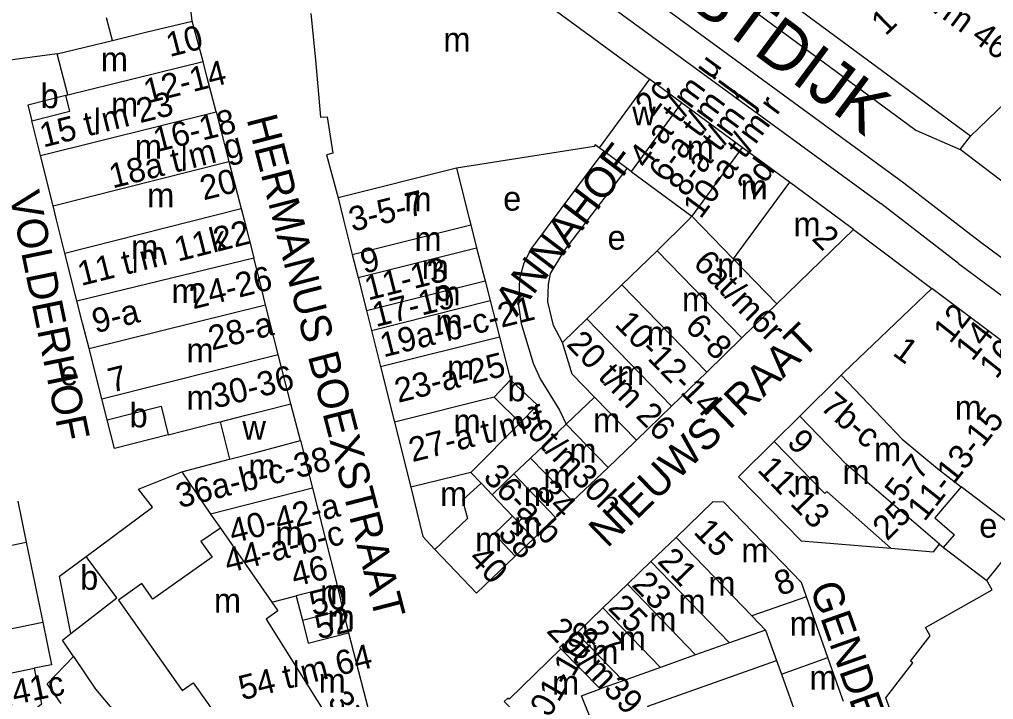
# Model space of a CAD drawing. Extents: x 160673 to 161924, y 382258 to 384145.
# Drawn here: x 161278.7 to 161438.4, y 383421.3 to 383532.8 of the extents above; entities that cross this region are included whole.
import ezdxf

# ---------------------------------------------------------------- set-up
doc = ezdxf.new("R2010")
doc.units = 0
for name, color, linetype in [('BLT_Basislijn', 7, 'Continuous'), ('BLT_Bebouwing', 7, 'Continuous'), ('BLT_Centroide', 7, 'Continuous'), ('BLT_Huisnummer', 7, 'Continuous'), ('BLT_Huisnummer_ tussenligend', 7, 'Continuous'), ('BLT_Huisnummer_reeks', 7, 'Continuous'), ('BLT_Onderdoorgang_en_onderverdeling', 7, 'Continuous'), ('BLT_Onderverdeling_panden', 7, 'Continuous'), ('BLT_Straatnaam', 7, 'Continuous'), ('BLT_Straatnaam_hoofdweg', 7, 'Continuous'), ('BLT_Vlakafsluiter', 7, 'Continuous')]:
    doc.layers.add(name, color=color, linetype=linetype)

msp = doc.modelspace()

# ---------------------------------------------------------------- linework, layer by layer
at = {"layer": 'BLT_Basislijn'}
msp.add_line((161430.2, 383446.26), (161437.31, 383440.84), dxfattribs=at)
for points in [[(161345.39, 383566.33), (161348.12, 383562.88), (161350.96, 383559.81), (161364.55, 383549.36), (161422.89, 383506.67), (161423.67, 383506.07)], [(161347.91, 383555.85), (161361.55, 383545.36), (161419.89, 383502.67)], [(161369.68, 383555.99), (161425.66, 383514.72), (161432.94, 383511.55)], [(161374.48, 383511.24), (161362.64, 383495.36), (161361.37, 383492.9), (161360.66, 383490.37), (161360.51, 383485.96), (161360.94, 383482.97), (161362.91, 383476.51), (161364.04, 383473.9), (161367.23, 383468.78), (161368.3, 383466.51)], [(161367.7, 383479.86), (161366.24, 383482.67), (161365.29, 383486.53), (161365.41, 383489.41), (161365.73, 383491.21), (161368.06, 383494.98), (161378.31, 383508.42)], [(161436.1, 383496.48), (161454.95, 383482.53), (161459.95, 383478.36), (161466.74, 383471.9), (161479.46, 383456.84), (161487.69, 383443.66), (161492.15, 383435.49)], [(161432.63, 383492.84), (161451.85, 383478.6), (161456.62, 383474.62), (161463.1, 383468.46), (161475.41, 383453.89), (161483.38, 383441.14), (161514.75, 383383.64)]]:
    msp.add_lwpolyline(points, dxfattribs=at)
at = {"layer": 'BLT_Bebouwing'}
for p, q in [((161307.01, 383532.58), (161305.61, 383544.29)), ((161354.7, 383543.03), (161376.75, 383526.88)), ((161308.77, 383525.95), (161307.01, 383532.58)), ((161326.43, 383533.81), (161327.24, 383526.25)), ((161284.87, 383527.21), (161270.68, 383525.31)), ((161376.75, 383526.88), (161381.98, 383523.04)), ((161387.23, 383519.16), (161381.98, 383523.04)), ((161286.25, 383520.38), (161286.6, 383520.47)), ((161397.18, 383511.85), (161387.23, 383519.16)), ((161310.92, 383517.7), (161313.02, 383509.56)), ((161282.12, 383510.56), (161280.7, 383516.22)), ((161373.71, 383511.81), (161373.08, 383512.28)), ((161404.93, 383506.15), (161397.18, 383511.85)), ((161284.19, 383502.28), (161282.12, 383510.56)), ((161378.31, 383508.42), (161374.48, 383511.24)), ((161313.02, 383509.56), (161315.02, 383501.84)), ((161378.96, 383507.94), (161378.31, 383508.42)), ((161378.96, 383507.94), (161388.92, 383500.6)), ((161352.66, 383499.2), (161353.63, 383495.43)), ((161402.88, 383486.22), (161415.45, 383498.42)), ((161288.1, 383486.74), (161286.13, 383494.52)), ((161333.25, 383494.32), (161334.2, 383490.55)), ((161353.63, 383495.43), (161355.02, 383490)), ((161377.47, 383489.34), (161383.23, 383494.93)), ((161317.96, 383490.35), (161317.08, 383493.79)), ((161319.04, 383486.08), (161317.96, 383490.35)), ((161334.2, 383490.55), (161335.57, 383485.11)), ((161355.02, 383490), (161355.85, 383486.76)), ((161371.7, 383483.74), (161377.47, 383489.34)), ((161447.99, 383473.94), (161428.25, 383488.75)), ((161289.03, 383483.06), (161288.1, 383486.74)), ((161321.1, 383477.92), (161319.04, 383486.08)), ((161355.85, 383486.76), (161357.37, 383480.83)), ((161397.12, 383480.62), (161402.88, 383486.22)), ((161335.57, 383485.11), (161336.38, 383481.86)), ((161290.08, 383478.91), (161289.03, 383483.06)), ((161367.7, 383479.86), (161371.7, 383483.74)), ((161336.38, 383481.86), (161337.87, 383475.93)), ((161357.37, 383480.83), (161359.18, 383473.77)), ((161391.36, 383475.03), (161397.12, 383480.62)), ((161292.18, 383470.65), (161290.08, 383478.91)), ((161323.15, 383469.83), (161321.1, 383477.92)), ((161337.87, 383475.93), (161340.17, 383466.82)), ((161385.59, 383469.43), (161391.36, 383475.03)), ((161413.4, 383474.51), (161406.61, 383467.78)), ((161293.05, 383467.19), (161292.18, 383470.65)), ((161368.3, 383466.51), (161372.94, 383470.93)), ((161324.75, 383463.8), (161323.15, 383469.83)), ((161379.83, 383463.84), (161385.59, 383469.43)), ((161310.75, 383466.69), (161311.57, 383466.9)), ((161311.57, 383466.9), (161313.13, 383460.74)), ((161406.61, 383467.78), (161402.45, 383463.67)), ((161303.06, 383464.74), (161310.75, 383466.69)), ((161360.76, 383466.71), (161352.71, 383458.55)), ((161362.48, 383460.94), (161368.3, 383466.51)), ((161324.75, 383463.8), (161326.72, 383455.99)), ((161305.27, 383458.7), (161313.13, 383460.74)), ((161359.74, 383458.33), (161362.48, 383460.94)), ((161369.37, 383453.85), (161375.2, 383459.41)), ((161352.71, 383458.55), (161354.39, 383456.79)), ((161356.17, 383454.92), (161359.74, 383458.33)), ((161326.72, 383455.99), (161330.76, 383440.04)), ((161354.39, 383456.79), (161356.17, 383454.92)), ((161433.1, 383456.22), (161428.75, 383451.14)), ((161278.41, 383453.87), (161279.79, 383447.15)), ((161366.57, 383451.17), (161369.37, 383453.85)), ((161363.01, 383447.77), (161366.57, 383451.17)), ((161428.75, 383451.14), (161431.99, 383448.34)), ((161359.97, 383444.87), (161363.01, 383447.77)), ((161386.34, 383447.93), (161382.22, 383443.96)), ((161430.2, 383446.26), (161431.99, 383448.34)), ((161279.79, 383447.15), (161282.48, 383434.02)), ((161382.22, 383443.96), (161378.35, 383440.23)), ((161330.76, 383440.04), (161331.71, 383436.03)), ((161378.35, 383440.23), (161374.35, 383436.37)), ((161438.17, 383439.33), (161437.31, 383440.84)), ((161411.23, 383428.23), (161407.71, 383438.2)), ((161331.71, 383436.03), (161332.65, 383432.28)), ((161374.35, 383436.37), (161370.08, 383432.24)), ((161332.65, 383432.28), (161336.29, 383418.13))]:
    msp.add_line(p, q, dxfattribs=at)
for points in [[(161434.59, 383513.69), (161370.22, 383561.27)], [(161450.34, 383528.87), (161434.59, 383513.69)], [(161286.6, 383520.47), (161284.87, 383527.21)], [(161327.24, 383526.25), (161328.05, 383516.81), (161329.1, 383516.91), (161330.05, 383510.93), (161329.02, 383510.67), (161330.92, 383503.58)], [(161310.92, 383517.7), (161309.42, 383523.48), (161308.77, 383525.95)], [(161286.25, 383520.38), (161280.05, 383518.79), (161280.7, 383516.22)], [(161373.08, 383512.28), (161372.91, 383512.04), (161350.32, 383508.45)], [(161374.48, 383511.24), (161373.96, 383511.63), (161373.71, 383511.81)], [(161350.32, 383508.45), (161352.46, 383500), (161352.66, 383499.2)], [(161415.45, 383498.42), (161413.3, 383500), (161404.93, 383506.15)], [(161286.13, 383494.52), (161284.77, 383500), (161284.19, 383502.28)], [(161330.92, 383503.58), (161331.82, 383500), (161333.25, 383494.32)], [(161315.02, 383501.84), (161315.49, 383500), (161317.08, 383493.79)], [(161383.23, 383494.93), (161388.39, 383500), (161388.92, 383500.6)], [(161428.25, 383488.75), (161413.87, 383474.97), (161413.4, 383474.51)], [(161372.94, 383470.93), (161369.29, 383474.69), (161367.7, 383479.86)], [(161359.18, 383473.77), (161363.6, 383469.58), (161360.76, 383466.71)], [(161303.06, 383464.74), (161294.24, 383462.5), (161293.05, 383467.19)], [(161340.17, 383466.82), (161342.85, 383456.15)], [(161375.2, 383459.41), (161379.49, 383463.51), (161379.83, 383463.84)], [(161402.45, 383463.67), (161396.6, 383457.88), (161406.84, 383447.36), (161421.58, 383446.15)], [(161289.6, 383444.8), (161300.47, 383452.88), (161298.21, 383455.82), (161305.27, 383458.7)], [(161342.85, 383456.15), (161344.83, 383448.05), (161346.77, 383445.92)], [(161443.34, 383448.4), (161433.1, 383456.22)], [(161407.71, 383438.2), (161406.89, 383440.52), (161394.17, 383453.71), (161392.37, 383453.75), (161386.34, 383447.93)], [(161437.31, 383440.84), (161443.34, 383448.4)], [(161421.58, 383446.15), (161428.55, 383445.58), (161429.54, 383446.81)], [(161429.54, 383446.81), (161430.2, 383446.26)], [(161287.12, 383432.15), (161285.26, 383441.57), (161289.6, 383444.8)], [(161346.77, 383445.92), (161353.59, 383438.78), (161359.97, 383444.87)], [(161428.73, 383399.62), (161420.71, 383421.64), (161425.14, 383427.34), (161424.78, 383427.61), (161427.99, 383431.78), (161427.23, 383433.15), (161438.17, 383439.33)], [(161282.48, 383434.02), (161283.91, 383427.04), (161281.07, 383426.46)], [(161287.51, 383428.42), (161285.72, 383431.07), (161287.12, 383432.15)], [(161370.08, 383432.24), (161367.96, 383430.21), (161367.81, 383430.45), (161367.21, 383429.87), (161367.45, 383429.66)], [(161367.45, 383429.66), (161358.98, 383421.38), (161358.74, 383421.59), (161358.13, 383421.03), (161358.29, 383420.86), (161359.67, 383419.42)], [(161285.52, 383420.68), (161283.19, 383423.93), (161287.51, 383428.42)], [(161413.8, 383421), (161411.94, 383426.23), (161411.23, 383428.23)], [(161281.07, 383426.46), (161282.28, 383420.56), (161279.09, 383417.99)]]:
    msp.add_lwpolyline(points, dxfattribs=at)
at = {"layer": 'BLT_Onderdoorgang_en_onderverdeling'}
for p, q in [((161381.98, 383523.04), (161373.71, 383511.81)), ((161387.23, 383519.16), (161378.96, 383507.94))]:
    msp.add_line(p, q, dxfattribs=at)
at = {"layer": 'BLT_Onderverdeling_panden'}
for p, q in [((161299.4, 383530.75), (161307.01, 383532.58)), ((161293.9, 383529.42), (161299.4, 383530.75)), ((161286.6, 383520.47), (161308.77, 383525.95)), ((161282.12, 383510.56), (161310.92, 383517.7)), ((161397.18, 383511.85), (161388.92, 383500.6)), ((161284.19, 383502.28), (161313.02, 383509.56)), ((161350.32, 383508.45), (161330.92, 383503.58)), ((161404.93, 383506.15), (161395.71, 383493.61)), ((161286.13, 383494.52), (161315.02, 383501.84)), ((161388.92, 383500.6), (161395.71, 383493.61)), ((161333.25, 383494.32), (161352.66, 383499.2)), ((161334.2, 383490.55), (161353.63, 383495.43)), ((161383.23, 383494.93), (161397.12, 383480.62)), ((161288.1, 383486.74), (161317.08, 383493.79)), ((161395.71, 383493.61), (161402.88, 383486.22)), ((161335.57, 383485.11), (161355.02, 383490)), ((161377.47, 383489.34), (161391.36, 383475.03)), ((161290.08, 383478.91), (161319.04, 383486.08)), ((161336.38, 383481.86), (161355.85, 383486.76)), ((161371.7, 383483.74), (161385.59, 383469.43)), ((161337.87, 383475.93), (161357.37, 383480.83)), ((161292.18, 383470.65), (161321.1, 383477.92)), ((161372.94, 383470.93), (161379.83, 383463.84)), ((161293.05, 383467.19), (161301.88, 383469.42)), ((161301.88, 383469.42), (161303.06, 383464.74)), ((161315.79, 383467.96), (161318.43, 383468.64)), ((161318.43, 383468.64), (161323.15, 383469.83)), ((161311.57, 383466.9), (161315.79, 383467.96)), ((161368.3, 383466.51), (161375.2, 383459.41)), ((161313.13, 383460.74), (161317.41, 383461.86)), ((161362.48, 383460.94), (161369.37, 383453.85)), ((161429.23, 383459.23), (161433.1, 383456.22)), ((161305.27, 383458.7), (161309.99, 383451.75)), ((161352.71, 383458.55), (161342.85, 383456.15)), ((161359.74, 383458.33), (161366.57, 383451.17)), ((161326.72, 383455.99), (161309.99, 383451.75)), ((161356.17, 383454.92), (161359.54, 383451.4)), ((161309.99, 383451.75), (161311.62, 383449.44)), ((161359.54, 383451.4), (161363.01, 383447.77)), ((161311.62, 383449.44), (161320.03, 383437.33)), ((161386.34, 383447.93), (161398.78, 383435.06)), ((161259.88, 383443.08), (161279.79, 383447.15)), ((161294.65, 383438), (161289.6, 383444.8)), ((161382.22, 383443.96), (161395.11, 383430.63)), ((161330.76, 383440.04), (161324.06, 383438.35)), ((161378.35, 383440.23), (161389.54, 383428.65)), ((161320.03, 383437.33), (161324.06, 383438.35)), ((161324.06, 383438.35), (161324.12, 383438.09)), ((161407.71, 383438.2), (161398.78, 383435.06)), ((161287.12, 383432.15), (161294.65, 383438)), ((161324.12, 383438.09), (161325.07, 383434.35)), ((161325.07, 383434.35), (161331.71, 383436.03)), ((161374.35, 383436.37), (161383.79, 383426.61)), ((161398.78, 383435.06), (161401.02, 383432.74)), ((161262.56, 383429.95), (161282.48, 383434.02)), ((161370.08, 383432.24), (161377.65, 383424.42)), ((161401.02, 383432.74), (161395.11, 383430.63)), ((161401.02, 383432.74), (161402.8, 383427.74)), ((161395.11, 383430.63), (161389.54, 383428.65)), ((161367.45, 383429.66), (161373.88, 383423.08)), ((161389.54, 383428.65), (161383.79, 383426.61)), ((161402.8, 383427.74), (161403.6, 383425.51)), ((161403.6, 383425.51), (161411.23, 383428.23)), ((161263.99, 383422.97), (161281.07, 383426.46)), ((161383.79, 383426.61), (161377.65, 383424.42)), ((161403.6, 383425.51), (161406.17, 383418.29)), ((161377.65, 383424.42), (161373.88, 383423.08))]:
    msp.add_line(p, q, dxfattribs=at)
for points in [[(161293.9, 383529.42), (161292.96, 383533.11)], [(161284.87, 383527.21), (161293.9, 383529.42)], [(161280.7, 383516.22), (161286.91, 383517.81), (161286.25, 383520.38)], [(161359.18, 383473.77), (161356.49, 383470.92), (161340.17, 383466.82)], [(161360.76, 383466.71), (161356.49, 383470.92), (161359.18, 383473.77)], [(161413.4, 383474.51), (161423.42, 383464.05), (161429.23, 383459.23)], [(161429.54, 383446.81), (161414.25, 383459.91), (161406.61, 383467.78)], [(161317.41, 383461.86), (161324.75, 383463.8)], [(161402.45, 383463.67), (161410.74, 383455.12), (161411.08, 383455.44), (161421.58, 383446.15)], [(161354.39, 383456.79), (161351.33, 383454.01), (161352.12, 383451.03), (161346.77, 383445.92)], [(161359.97, 383444.87), (161356.51, 383448.5), (161359.54, 383451.4)], [(161311.62, 383449.44), (161308.43, 383447.26), (161310.25, 383444.66), (161300.53, 383437.82), (161298.75, 383440.35), (161294.9, 383437.64), (161305.36, 383422.81), (161307.15, 383424.08), (161319.74, 383406.42)], [(161320.03, 383437.33), (161321.05, 383435.86), (161319.13, 383434.53), (161331.52, 383414.75)], [(161325.07, 383434.35), (161326.01, 383430.6), (161332.65, 383432.28)], [(161287.51, 383428.42), (161291.14, 383423.03), (161295.87, 383417.4), (161309.52, 383398.77)], [(161375.84, 383403.65), (161383.36, 383416.18), (161381.72, 383420.23), (161402.8, 383427.74)], [(161372.33, 383418.28), (161370.84, 383421.95), (161373.64, 383422.99), (161373.88, 383423.08)]]:
    msp.add_lwpolyline(points, dxfattribs=at)
at = {"layer": 'BLT_Vlakafsluiter'}
for p, q in [((161432.94, 383511.55), (161434.59, 383513.69)), ((161443.28, 383503.61), (161432.94, 383511.55)), ((161423.67, 383506.07), (161436.1, 383496.48)), ((161432.63, 383492.84), (161419.89, 383502.67)), ((161415.45, 383498.42), (161428.25, 383488.75))]:
    msp.add_line(p, q, dxfattribs=at)

# ---------------------------------------------------------------- texts
at = {"layer": 'BLT_Centroide'}
for s, p in [('m', (161348.18, 383527.58)), ('m', (161292.01, 383524.35)), ('b', (161282.14, 383518.31)), ('m', (161293.68, 383516.93)), ('w', (161379.14, 383515.5)), ('m', (161297.59, 383510)), ('m', (161388.08, 383509.88)), ('m', (161396.92, 383503.38)), ('m', (161299.61, 383502.03)), ('m', (161341.79, 383501.38)), ('e', (161357.98, 383501.5)), ('m', (161405.58, 383497.27)), ('m', (161343.43, 383494.88)), ('e', (161375.1, 383495.11)), ('m', (161296.99, 383493.55)), ('m', (161344.61, 383490.28)), ('m', (161393.05, 383490.58)), ('m', (161303.59, 383486.34)), ('m', (161346.54, 383485.95)), ('m', (161387.3, 383484.98)), ('m', (161346.88, 383481.34)), ('m', (161381.53, 383479.39)), ('m', (161306.05, 383476.62)), ('m', (161348.79, 383473.81)), ('e', (161285.32, 383472.85)), ('m', (161376.66, 383472.89)), ('b', (161358.71, 383470.25)), ('m', (161306.05, 383468.87)), ('b', (161296.72, 383465.97)), ('m', (161432.03, 383467.22)), ('w', (161315.22, 383463.94)), ('m', (161349.84, 383464.97)), ('m', (161372.73, 383465.17)), ('m', (161368.84, 383460.19)), ('m', (161418.81, 383460.38)), ('m', (161316.2, 383457.62)), ('m', (161364.56, 383456.05)), ('m', (161413.62, 383456.69)), ('m', (161405.59, 383454.91)), ('m', (161347.64, 383453.07)), ('m', (161361.38, 383453.05)), ('m', (161359.77, 383448.12)), ('e', (161436.05, 383447.89)), ('m', (161320.66, 383446.61)), ('m', (161353.38, 383445.62)), ('m', (161397.03, 383443.81)), ('b', (161288.62, 383439.33)), ('m', (161391.62, 383438.36)), ('m', (161327.98, 383436.97)), ('m', (161310.56, 383435.59)), ('m', (161386.73, 383435.44)), ('m', (161329.19, 383432.84)), ('m', (161381.95, 383432.5)), ('m', (161404.95, 383431.79)), ('m', (161376.94, 383429.42)), ('m', (161372.44, 383427.19)), ('m', (161327.72, 383422.45)), ('m', (161408.21, 383422.94)), ('m', (161366, 383422.12))]:
    msp.add_text(s, height=4, dxfattribs=at).set_placement(p)
at = {"layer": 'BLT_Huisnummer'}
for s, rotation, p in [('10', 14.4023, (161303.3, 383526.67)), ('2d', 53.6786, (161399.2, 383503.45)), ('20', 14.1427, (161308.86, 383503.17)), ('2', 314.1573, (161408.46, 383496.8)), ('9', 14.1181, (161335.15, 383491.14)), ('19a-b-c-21', 14.1165, (161338.36, 383477.42)), ('38', 313.6899, (161356.95, 383448.39)), ('40', 313.68, (161352.12, 383444.3)), ('21', 314.0269, (161383.13, 383443.88)), ('50', 14.181, (161326.8, 383435.04)), ('52', 14.1728, (161327.71, 383431.17)), ('27', 314.0269, (161370.97, 383432.16))]:
    msp.add_text(s, height=4, rotation=rotation, dxfattribs=at).set_placement(p)
at = {"layer": 'BLT_Huisnummer_ tussenligend'}
for s, rotation, p in [('23', 314.0248, (161378.92, 383440.04)), ('25', 314.0266, (161375.02, 383436.23))]:
    msp.add_text(s, height=4, rotation=rotation, dxfattribs=at).set_placement(p)
at = {"layer": 'BLT_Huisnummer_reeks'}
for s, rotation, p in [('40 t/m 46', 323.5247, (161421.39, 383539.32)), ('1', 44.1939, (161420.7, 383530.04)), ('12-14', 14.1421, (161299.6, 383519.04)), ('4-a t/m u', 53.6777, (161381.5, 383508.2)), ('6-a t/m j', 53.6777, (161384.75, 383505.87)), ('2c', 53.6786, (161382.51, 383516.75)), ('8-a t/m j', 53.6777, (161388, 383503.55)), ('15 t/m 23', 14.1421, (161282.57, 383511.83)), ('10-a t/m r', 53.6777, (161390.35, 383499.99)), ('16-18', 14.1424, (161301.2, 383511.08)), ('18a t/m g', 14.1424, (161293.94, 383505.13)), ('3-5-7', 14.1154, (161333.26, 383498.02)), ('11 t/m 11k', 14.1412, (161288.78, 383489.13)), ('22', 14.1412, (161311.05, 383494.73)), ('6at/m6r', 314.1548, (161388.96, 383492.69)), ('24-26', 14.2298, (161307.15, 383485.31)), ('11-13', 14.1173, (161335.84, 383486.76)), ('17-19', 14.1166, (161337.11, 383482.39)), ('9-a', 14.2298, (161291.15, 383481.37)), ('12', 51.7131, (161431.3, 383479.54)), ('10-12-14', 314.1527, (161376.12, 383482.74)), ('28-a', 14.1412, (161310.22, 383478.56)), ('6-8', 314.1527, (161387.61, 383482.29)), ('14', 51.7112, (161434.92, 383476.66)), ('20 t/m 26', 314.1563, (161368.2, 383479.47)), ('1', 323.6774, (161421.67, 383477.94)), ('16', 51.7113, (161438.84, 383473.74)), ('23-a-25', 14.2088, (161340.76, 383469.96)), ('7', 14.2164, (161293.78, 383471.64)), ('30-36', 14.1412, (161310.71, 383469.03)), ('7b-c', 319.4916, (161409.78, 383469.08)), ('27-a t/m f', 14.225, (161343.09, 383460.24)), ('30t/m30h', 314.1852, (161359.61, 383467.22)), ('11-13-15', 51.7128, (161427.05, 383450.38)), ('9', 314.1461, (161404.34, 383463.34)), ('36a-b-c-38', 14.2253, (161304.91, 383452.7)), ('11-13', 314.2217, (161399.5, 383458.9)), ('5-7', 51.7128, (161423.35, 383453.39)), ('36-a-b', 313.6857, (161354.54, 383457.66)), ('34', 313.6857, (161363.28, 383455.08)), ('40-42-a', 14.2253, (161313.62, 383446.91)), ('25', 44.7044, (161420.96, 383447.24)), ('44-a-b-c', 14.181, (161312.83, 383442.04)), ('15', 314.0245, (161389.04, 383448.69)), ('46', 13.8585, (161323.77, 383439.8)), ('8', 19.3477, (161403.33, 383438.29)), ('101-103', 59.8452, (161364.07, 383415.6)), ('29t/m39', 314.0269, (161364.95, 383432.47)), ('54 t/m 64', 14.1728, (161315.18, 383421.2)), ('41tm41c', 11.555, (161266.21, 383418.1)), ('37', 301.5469, (161329.08, 383421.22))]:
    msp.add_text(s, height=4, rotation=rotation, dxfattribs=at).set_placement(p)
at = {"layer": 'BLT_Straatnaam'}
for s, height, rotation, p in [('HERMANUS BOEXSTRAAT', 4.9999, 284.4784, (161315.89, 383516.54)), ('ANNAHOF', 5, 52.7998, (161360.19, 383483.96)), ('VOLDERHOF', 5, 281.593, (161276.99, 383504.16)), ('NIEUWSTRAAT', 5, 44.0239, (161375.03, 383446.05)), ('GENDERSTRAATJE', 4.9999, 289.3989, (161408.21, 383439.72))]:
    msp.add_text(s, height=height, rotation=rotation, dxfattribs=at).set_placement(p)
at = {"layer": 'BLT_Straatnaam_hoofdweg'}
msp.add_text('VESTDIJK', height=8, rotation=323.4144, dxfattribs=at).set_placement((161376.35, 383544.02))

doc.saveas('drawing.dxf')
